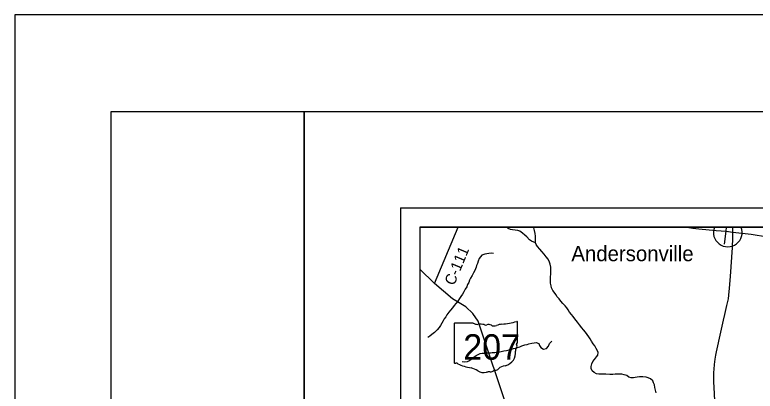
# Model space of a CAD drawing. Extents: x 0 to 34, y 0 to 22.
# Drawn here: x 0 to 3.839, y 20.051 to 22 of the extents above; entities that cross this region are included whole.
import ezdxf

# ---------------------------------------------------------------- set-up
doc = ezdxf.new("R2010")
doc.units = 0
for name, color, linetype in [('GM_X_Corporation', 7, 'Continuous'), ('GM_X_County_Road', 7, 'Continuous'), ('GM_X_County_Road_Text', 7, 'Continuous'), ('GM_X_Minor_River', 7, 'Continuous'), ('GM_X_State_Location', 7, 'Continuous'), ('GM_X_State_Route', 7, 'Continuous'), ('GM_X_State_Shield', 7, 'Continuous'), ('GM_X_Township_Road', 7, 'Continuous'), ('GM_X_Unincorporated_Location', 7, 'Continuous'), ('GM_X_Unincorporated_Text', 7, 'Continuous'), ('SH_Border', 7, 'Continuous'), ('SH_Cut_Line', 7, 'Continuous'), ('SH_Data', 7, 'Continuous')]:
    doc.layers.add(name, color=color, linetype=linetype)

msp = doc.modelspace()

# ---------------------------------------------------------------- linework, layer by layer
at = {"layer": 'GM_X_Corporation'}
msp.add_line((2.1, 20.9), (2.1, 15.8164), dxfattribs=at)
msp.add_lwpolyline([(4.892, 20.9), (2.1, 20.9), (2.1, 15.9991)], dxfattribs=at)
at = {"layer": 'GM_X_County_Road'}
msp.add_line((2.1759, 20.6081), (2.2987, 20.9), dxfattribs=at)
at = {"layer": 'GM_X_Minor_River'}
for points in [[(2.7002, 20.8199), (2.6911, 20.8219), (2.679, 20.8281), (2.6688, 20.8346), (2.6545, 20.8495), (2.6448, 20.8584), (2.632, 20.8699), (2.6192, 20.8791), (2.6086, 20.8826), (2.5946, 20.885), (2.581, 20.8866), (2.5696, 20.8883), (2.5587, 20.894), (2.5521, 20.9)], [(2.8947, 20.4373), (2.8873, 20.4484), (2.8768, 20.4602), (2.8685, 20.4725), (2.8618, 20.482), (2.8535, 20.4931), (2.8419, 20.5053), (2.831, 20.5172), (2.822, 20.529), (2.8126, 20.5401), (2.8051, 20.5508), (2.7965, 20.563), (2.7894, 20.5729), (2.7834, 20.5863), (2.7809, 20.5973), (2.778, 20.6095), (2.7769, 20.6231), (2.7774, 20.6341), (2.7783, 20.6447), (2.7795, 20.6557), (2.7797, 20.6804), (2.7787, 20.6933), (2.7758, 20.7081), (2.7724, 20.7187), (2.7654, 20.7344), (2.7552, 20.747), (2.7455, 20.76), (2.7327, 20.7749), (2.7222, 20.7867), (2.7102, 20.8005), (2.7031, 20.81), (2.7002, 20.8199), (2.7006, 20.8317), (2.7004, 20.8438), (2.6993, 20.8541), (2.6979, 20.867), (2.6954, 20.8825), (2.6909, 20.8962), (2.6895, 20.9)], [(2.4814, 20.7639), (2.4708, 20.7655), (2.4582, 20.7641), (2.4472, 20.7627), (2.437, 20.7613), (2.4218, 20.755), (2.4076, 20.7388), (2.4022, 20.7244), (2.3987, 20.7127), (2.3948, 20.7025), (2.3917, 20.6927), (2.3847, 20.6756), (2.3778, 20.6643), (2.3709, 20.6504), (2.3635, 20.636), (2.3581, 20.6251), (2.3535, 20.6145), (2.3477, 20.6039), (2.3431, 20.5907), (2.3358, 20.5794), (2.3281, 20.5662), (2.3215, 20.5537), (2.3131, 20.5405), (2.3066, 20.5307), (2.297, 20.5175), (2.2866, 20.5051), (2.2782, 20.4949), (2.269, 20.4817), (2.2591, 20.4708), (2.2506, 20.4603), (2.2403, 20.4467), (2.2353, 20.4365), (2.2268, 20.4252), (2.2214, 20.4147), (2.2149, 20.4034), (2.2068, 20.3909), (2.2007, 20.3811), (2.1907, 20.3691), (2.1762, 20.3548), (2.1621, 20.3447), (2.1518, 20.3364), (2.1415, 20.3289)], [(3.3265, 20.0431), (3.3224, 20.0568), (3.3195, 20.0697), (3.3162, 20.0834), (3.3125, 20.0933), (3.3077, 20.1039), (3.2957, 20.115), (3.2839, 20.1197), (3.273, 20.1236), (3.2563, 20.1256), (3.2396, 20.125), (3.2271, 20.1229), (3.2169, 20.1211), (3.2074, 20.12), (3.1968, 20.1197), (3.1839, 20.124), (3.173, 20.1313), (3.1605, 20.136), (3.1477, 20.1384), (3.1363, 20.1385), (3.1268, 20.139), (3.1139, 20.1383), (3.1014, 20.1381), (3.0855, 20.1378), (3.0654, 20.1384), (3.0434, 20.1386), (3.0275, 20.1387), (3.0162, 20.1411), (3.0041, 20.1473), (2.9936, 20.1569), (2.988, 20.1687), (2.9881, 20.1782), (2.9912, 20.1922), (2.9978, 20.2043), (3.0058, 20.2156), (3.0162, 20.2284), (3.0234, 20.2382), (3.0243, 20.2507), (3.0206, 20.2606), (3.0139, 20.2716), (3.0068, 20.2853), (2.9997, 20.2964), (2.9899, 20.3101), (2.9828, 20.3223), (2.9761, 20.3323), (2.9679, 20.3441), (2.9589, 20.3571), (2.948, 20.3682), (2.9394, 20.3796), (2.9281, 20.3945), (2.9184, 20.4083), (2.9041, 20.4259), (2.8947, 20.4373)], [(2.3189, 20.2048), (2.3333, 20.2031), (2.347, 20.2053), (2.3577, 20.2097), (2.3672, 20.2161), (2.3809, 20.2266), (2.3931, 20.236), (2.403, 20.2416), (2.4125, 20.2453), (2.4239, 20.2474), (2.4349, 20.2481), (2.4478, 20.2491), (2.466, 20.2501), (2.4755, 20.2504), (2.4891, 20.2514), (2.4986, 20.2528), (2.5127, 20.255), (2.5222, 20.2572), (2.5366, 20.2597), (2.5499, 20.2622), (2.5632, 20.2659), (2.586, 20.2718), (2.5958, 20.2739), (2.6069, 20.2772), (2.6179, 20.2813), (2.6285, 20.2858), (2.6449, 20.2906), (2.6559, 20.2935), (2.6658, 20.2964), (2.6802, 20.2997), (2.6923, 20.3015), (2.7026, 20.3022), (2.7166, 20.2975), (2.7214, 20.288), (2.7274, 20.2765), (2.7421, 20.268), (2.7565, 20.2721), (2.7676, 20.2837), (2.773, 20.2981), (2.7841, 20.3098)]]:
    msp.add_lwpolyline(points, dxfattribs=at)
at = {"layer": 'GM_X_State_Route'}
for points in [[(3.6819, 20.4482), (3.6923, 20.494), (3.6999, 20.53), (3.7026, 20.5489), (3.7067, 20.5836), (3.7116, 20.6449), (3.7212, 20.7955), (3.7236, 20.845), (3.7236, 20.8751), (3.7232, 20.9)], [(2.9152, 19.41), (2.6475, 19.8161), (2.5621, 19.9394), (2.4022, 20.4134), (2.3745, 20.454), (2.3388, 20.4877), (2.2702, 20.5289), (2.1759, 20.6081), (2.1, 20.6834)], [(3.6216, 19.7741), (3.6251, 19.7939), (3.628, 19.8136), (3.632, 19.8534), (3.6329, 19.8885), (3.6326, 19.9177), (3.6277, 20.0383), (3.625, 20.0992), (3.625, 20.1253), (3.6253, 20.1473), (3.6263, 20.1648), (3.6286, 20.189), (3.6318, 20.2167), (3.6349, 20.2376), (3.6382, 20.2546), (3.6609, 20.3565), (3.675, 20.418), (3.6819, 20.4482)]]:
    msp.add_lwpolyline(points, dxfattribs=at)
at = {"layer": 'GM_X_State_Shield'}
for p, q in [((3.7665, 20.9), (3.6278, 20.9)), ((2.2775, 20.3999), (2.2775, 20.1998)), ((2.3773, 20.4034), (2.2808, 20.4034)), ((2.6071, 20.3037), (2.6071, 20.4083)), ((2.6071, 20.3037), (2.6071, 20.3037))]:
    msp.add_line(p, q, dxfattribs=at)
msp.add_arc((3.6971, 20.873), 0.0744, 158.7596, 21.2404, dxfattribs=at)
for centre, major_axis, start_param, end_param in [((2.2813, 20.4004), (0.00382, 0), 1.712693, 3.28349), ((2.4003, 20.4266), (0.037, 0), 4.042523, 4.731795), ((2.4126, 20.291), (0.133, 0), 1.404758, 1.657858), ((2.4428, 20.4014), (0.0107, 0), 3.836095, 5.185415), ((2.4584, 20.3783), (0.0222, 0), 0.950623, 2.079405), ((2.4871, 20.41), (0.0267, 0), 4.081561, 5.145723), ((2.5343, 20.3423), (0.0703, 0), 1.699011, 2.107814), ((2.4897, 20.6762), (0.3495, 0), 4.814394, 5.042369), ((2.6035, 20.4088), (0.00367, 0), 6.141152, 7.989035), ((2.6203, 20.2598), (0.0248, 0), 2.387724, 3.262537), ((2.6063, 20.296), (0.00568, 0), 1.883978, 3.671073), ((2.5702, 20.2827), (0.0341, 0), 5.934695, 6.695948), ((2.6032, 20.3033), (0.00393, 0), 5.05454, 6.418171), ((2.5093, 20.2465), (0.0874, 0), 5.101752, 6.440018), ((2.2814, 20.1994), (0.00385, 0), 3.00124, 4.508301), ((2.2819, 20.2199), (0.0294, 0), 4.665946, 4.897461), ((2.2879, 20.1883), (0.0106, 0), 0.519207, 1.627899), ((2.4218, 20.3681), (0.2524, 0), 4.195997, 4.488961), ((2.3465, 20.1099), (0.079, 0), 0.823519, 1.323587), ((2.4319, 20.1873), (0.0501, 0), 4.026481, 4.996735), ((2.4646, 20.1723), (0.0267, 0), 4.691044, 5.507374), ((2.4887, 20.1529), (0.00752, 0), 1.147584, 2.315152), ((2.4855, 20.1804), (0.0282, 0), 4.937069, 5.64225), ((2.5462, 20.1436), (0.0479, 0), 1.647645, 2.488434), ((2.4609, 20.1181), (0.0412, 0), 1.495662, 1.94098)]:
    msp.add_ellipse(centre, major_axis=major_axis, ratio=0.8, start_param=start_param, end_param=end_param, dxfattribs=at)
at = {"layer": 'GM_X_Township_Road'}
for points in [[(3.4918, 20.9), (3.4951, 20.899), (3.5165, 20.8944), (3.5474, 20.8909), (3.6368, 20.8822), (3.688, 20.8795), (3.7236, 20.8751)], [(3.6804, 20.8115), (3.688, 20.8795), (3.6899, 20.9)], [(3.7236, 20.8751), (3.8187, 20.8634), (3.9038, 20.851), (3.9179, 20.8487), (3.9315, 20.8493), (3.9417, 20.8533), (3.9679, 20.866), (4.0265, 20.9)]]:
    msp.add_lwpolyline(points, dxfattribs=at)
at = {"layer": 'GM_X_Unincorporated_Location'}
msp.add_line((3.6971, 20.873), (3.6971, 20.873), dxfattribs=at)
at = {"layer": 'SH_Border'}
for points in [[(0.5, 21.5), (1.5, 21.5), (1.5, 0.5), (0.5, 0.5)], [(1.5, 21.5), (33.5, 21.5), (33.5, 0.5), (1.5, 0.5)]]:
    msp.add_lwpolyline(points, close=True, dxfattribs=at)
at = {"layer": 'SH_Cut_Line'}
msp.add_lwpolyline([(0, 0), (34, 0), (34, 22), (0, 22)], close=True, dxfattribs=at)
at = {"layer": 'SH_Data'}
for p, q in [((2, 21), (9, 21)), ((2, 21), (2, 14)), ((2.1, 20.9), (2.1, 14.1)), ((2.1, 20.9), (8.9, 20.9)), ((2.2775, 20.3999), (2.2775, 20.1998)), ((2.3773, 20.4034), (2.2808, 20.4034)), ((2.6071, 20.3037), (2.6071, 20.4083)), ((2.6071, 20.3037), (2.6071, 20.3037))]:
    msp.add_line(p, q, dxfattribs=at)
for centre, major_axis, start_param, end_param in [((2.2813, 20.4004), (0.00382, 0), 1.712693, 3.28349), ((2.4003, 20.4266), (0.037, 0), 4.042523, 4.731795), ((2.4126, 20.291), (0.133, 0), 1.404758, 1.657858), ((2.4428, 20.4014), (0.0107, 0), 3.836095, 5.185415), ((2.4584, 20.3783), (0.0222, 0), 0.950623, 2.079405), ((2.4871, 20.41), (0.0267, 0), 4.081561, 5.145723), ((2.5343, 20.3423), (0.0703, 0), 1.699011, 2.107814), ((2.4897, 20.6762), (0.3495, 0), 4.814394, 5.042369), ((2.6035, 20.4088), (0.00367, 0), 6.141152, 7.989035), ((2.6203, 20.2598), (0.0248, 0), 2.387724, 3.262537), ((2.6063, 20.296), (0.00568, 0), 1.883978, 3.671073), ((2.5702, 20.2827), (0.0341, 0), 5.934695, 6.695948), ((2.6032, 20.3033), (0.00393, 0), 5.05454, 6.418171), ((2.5093, 20.2465), (0.0874, 0), 5.101752, 6.440018), ((2.2814, 20.1994), (0.00385, 0), 3.00124, 4.508301), ((2.2819, 20.2199), (0.0294, 0), 4.665946, 4.897461), ((2.2879, 20.1883), (0.0106, 0), 0.519207, 1.627899), ((2.4218, 20.3681), (0.2524, 0), 4.195997, 4.488961), ((2.3465, 20.1099), (0.079, 0), 0.823519, 1.323587), ((2.4319, 20.1873), (0.0501, 0), 4.026481, 4.996735), ((2.4646, 20.1723), (0.0267, 0), 4.691044, 5.507374), ((2.4887, 20.1529), (0.00752, 0), 1.147584, 2.315152), ((2.4855, 20.1804), (0.0282, 0), 4.937069, 5.64225), ((2.5462, 20.1436), (0.0479, 0), 1.647645, 2.488434), ((2.4609, 20.1181), (0.0412, 0), 1.495662, 1.94098)]:
    msp.add_ellipse(centre, major_axis=major_axis, ratio=0.8, start_param=start_param, end_param=end_param, dxfattribs=at)

# ---------------------------------------------------------------- texts
at = {"layer": 'GM_X_County_Road_Text'}
msp.add_text('C-111', height=0.05682, rotation=67.3794, dxfattribs=at).set_placement((2.2779, 20.5945))
at = {"layer": 'GM_X_State_Location'}
msp.add_text('207', height=0.000189, rotation=0, dxfattribs=at).set_placement((2.3718, 20.2728))
for s in ['s', 'r']:
    msp.add_text(s, height=0.000189, dxfattribs=at).set_placement((2.4386, 20.2866))
at = {"layer": 'GM_X_State_Shield'}
msp.add_text('207', height=0.13184, dxfattribs=at).set_placement((2.3254, 20.2139))
at = {"layer": 'GM_X_Unincorporated_Text'}
msp.add_text('Andersonville', height=0.078977, rotation=0, dxfattribs=at).set_placement((2.8859, 20.7241))
at = {"layer": 'SH_Data'}
msp.add_text('207', height=0.13184, dxfattribs=at).set_placement((2.3254, 20.2139))

doc.saveas('drawing.dxf')
